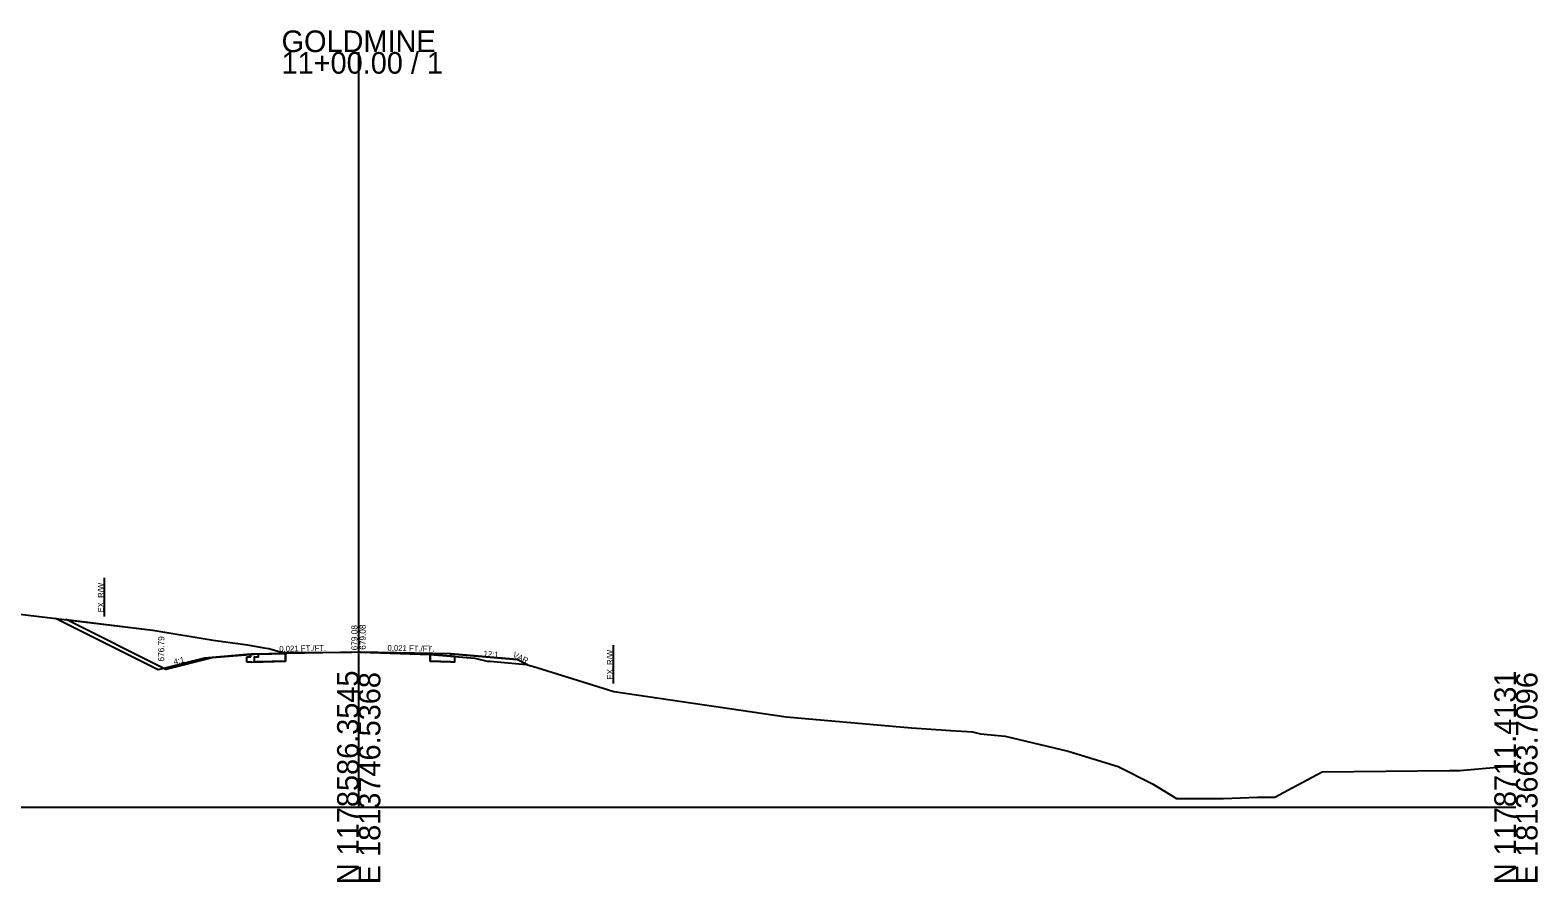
# Model space of a CAD drawing. Extents: x -26 to 1603, y -10 to 1590.
# Drawn here: x 1407.4 to 1602.8, y 490.3 to 600.7 of the extents above; entities that cross this region are included whole.
import ezdxf

# ---------------------------------------------------------------- set-up
doc = ezdxf.new("R2010")
doc.units = 0
for name, color, linetype in [('Default', 7, 'Continuous'), ('RD_EX_RW', 7, 'Continuous'), ('RD_GPK_XS_Cell', 7, 'Continuous'), ('RD_XS_Base', 7, 'Continuous'), ('RD_XS_EarthShd', 7, 'Continuous'), ('RD_XS_ExGround', 7, 'Continuous'), ('RD_XS_Misc_Line', 7, 'Continuous'), ('RD_XS_Pave', 7, 'Continuous'), ('RD_XS_TieSlope', 7, 'Continuous'), ('RD_XS_TX_Elev_EX', 7, 'Continuous'), ('RD_XS_TX_Elev_PR', 7, 'Continuous'), ('RD_XS_TX_Slope', 7, 'Continuous')]:
    doc.layers.add(name, color=color, linetype=linetype)

msp = doc.modelspace()

# ---------------------------------------------------------------- linework, layer by layer
at = {"layer": 'Default'}
for p, q in [((1450, 520.08), (1436, 519.79)), ((1461.95, 519.83), (1450, 520.08))]:
    msp.add_line(p, q, dxfattribs=at)
at = {"layer": 'RD_EX_RW'}
for p, q in [((1417, 529.68), (1417, 524.68)), ((1483, 520.99), (1483, 515.99))]:
    msp.add_line(p, q, dxfattribs=at)
at = {"layer": 'RD_GPK_XS_Cell'}
for p, q in [((1450, 500), (1450, 597.82)), ((1300, 500), (1450, 500)), ((1450, 500), (1600, 500))]:
    msp.add_line(p, q, dxfattribs=at)
at = {"layer": 'RD_XS_Base'}
for p, q in [((1440.5, 518.88), (1440.5, 519.88)), ((1436.16, 518.79), (1440.5, 518.88)), ((1459.24, 518.89), (1459.24, 519.78)), ((1461.95, 518.83), (1459.24, 518.89))]:
    msp.add_line(p, q, dxfattribs=at)
at = {"layer": 'RD_XS_EarthShd'}
for p, q in [((1436, 519.79), (1430, 519.29)), ((1461.95, 519.83), (1470.53, 519.12))]:
    msp.add_line(p, q, dxfattribs=at)
at = {"layer": 'RD_XS_ExGround'}
msp.add_lwpolyline([(1405.74, 525.04), (1422.56, 523.01), (1423.32, 522.92), (1431.14, 521.61), (1435.58, 521), (1437.7, 520.64), (1438.34, 520.56), (1439.82, 520.12), (1440.5, 520.01), (1449.14, 520.08), (1449.76, 520.09), (1459.24, 519.78), (1465.03, 519.27), (1466.65, 518.92), (1466.98, 518.88), (1471.73, 518.48), (1473.07, 518.07), (1483.07, 514.98), (1505.41, 511.69), (1521.66, 510.25), (1526.73, 509.91), (1529.55, 509.76), (1530.59, 509.49), (1533.8, 509.18), (1541.98, 507.22), (1548.44, 505.23), (1552.89, 503.02), (1556.01, 501.09), (1559.86, 501.09), (1562.11, 501.11), (1566.49, 501.28), (1568.74, 501.29), (1570.44, 502.18), (1574.89, 504.54), (1591.37, 504.75), (1591.89, 504.74), (1592.72, 504.72), (1600, 505.38)], dxfattribs=at)
at = {"layer": 'RD_XS_Misc_Line'}
for points in [[(1449.76, 520.09), (1450.18, 520.08), (1450, 520.08), (1440.5, 519.88), (1437, 519.81), (1431, 519.31), (1425, 517.81), (1412.07, 524.28), (1422.56, 523.01), (1423.32, 522.92), (1431.14, 521.61), (1435.58, 521), (1437.7, 520.64), (1438.34, 520.56), (1439.82, 520.12), (1440.5, 520.01), (1449.14, 520.08)], [(1437, 518.81), (1436.5, 518.8), (1436.5, 519.47), (1437, 519.48), (1437, 519.81), (1440.5, 519.88), (1440.5, 518.88)], [(1461.95, 519.54), (1461.95, 519.83), (1450.18, 520.08), (1459.24, 519.78)], [(1462.45, 519.49), (1461.95, 519.5), (1461.95, 519.54), (1459.24, 519.78), (1459.24, 518.89), (1461.95, 518.83), (1462.45, 518.82)], [(1461.95, 519.54), (1462.45, 519.49), (1465.03, 519.27), (1466.65, 518.92), (1466.98, 518.88), (1471.73, 518.48), (1470.53, 519.12), (1461.95, 519.83)], [(1461.95, 519.54), (1462.45, 519.49), (1461.95, 519.5)]]:
    msp.add_lwpolyline(points, close=True, dxfattribs=at)
at = {"layer": 'RD_XS_Pave'}
for p, q in [((1435.5, 519.45), (1436, 519.46)), ((1435.5, 518.78), (1435.5, 519.45)), ((1436.16, 518.79), (1435.5, 518.78)), ((1436, 519.46), (1436, 519.79)), ((1461.95, 519.5), (1461.95, 519.83)), ((1462.45, 519.49), (1461.95, 519.5)), ((1461.95, 518.83), (1462.45, 518.82)), ((1462.45, 518.82), (1462.45, 519.49))]:
    msp.add_line(p, q, dxfattribs=at)
at = {"layer": 'RD_XS_TieSlope'}
for p, q in [((1424, 517.79), (1410.7, 524.44)), ((1430, 519.29), (1424, 517.79)), ((1471.73, 518.48), (1470.53, 519.12))]:
    msp.add_line(p, q, dxfattribs=at)

# ---------------------------------------------------------------- texts
at = {"layer": 'Default'}
msp.add_text(' 679.08', height=0.8, rotation=90, dxfattribs=at).set_placement((1450.91, 520.08))
at = {"layer": 'RD_EX_RW'}
for p in [(1416.94, 525.21), (1482.94, 516.52)]:
    msp.add_text('EX. R/W', height=0.75, rotation=90, dxfattribs=at).set_placement(p)
at = {"layer": 'RD_GPK_XS_Cell'}
for s, p in [('GOLDMINE', (1440, 597.82)), ('11+00.00 / 1', (1440, 595.02))]:
    msp.add_text(s, height=2.8, dxfattribs=at).set_placement(p)
for s, p in [('N 1178586.3545', (1450, 490)), ('E 1813746.5368', (1452.8, 490)), ('N 1178711.4131', (1600, 490)), ('E 1813663.7096', (1602.8, 490))]:
    msp.add_text(s, height=2.8, rotation=90, dxfattribs=at).set_placement(p)
at = {"layer": 'RD_XS_TX_Elev_EX'}
msp.add_text('679.08', height=0.8, rotation=90, dxfattribs=at).set_placement((1449.84, 520.3))
at = {"layer": 'RD_XS_TX_Elev_PR'}
msp.add_text('676.79', height=0.8, rotation=90, dxfattribs=at).set_placement((1424.8, 518.85))
at = {"layer": 'RD_XS_TX_Slope'}
for s, rotation, p in [('0.021 FT./FT.', 1.1916, (1439.71, 520.12)), ('0.021 FT./FT.', 358.8084, (1453.72, 520.25)), ('12:1', 354.4902, (1466.15, 519.53)), ('VAR.', 333.1331, (1469.9, 519.49)), ('4:1', 14.0362, (1426.11, 518.44))]:
    msp.add_text(s, height=0.75, rotation=rotation, dxfattribs=at).set_placement(p)

doc.saveas('drawing.dxf')
